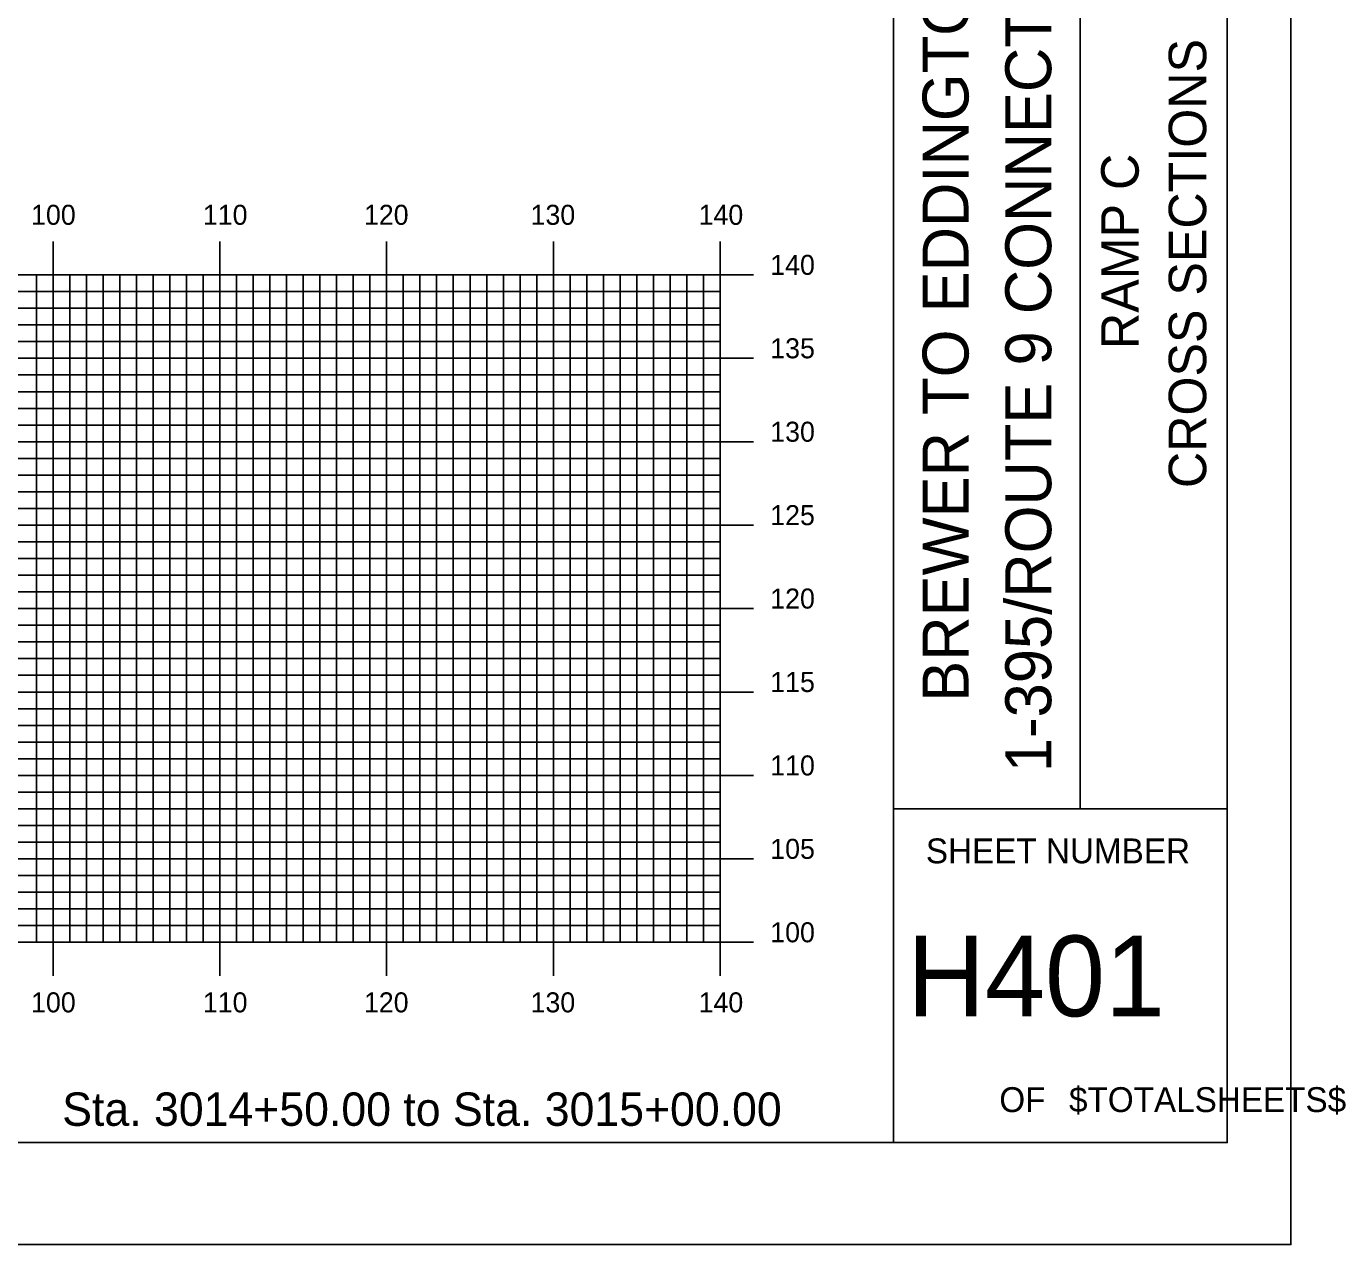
# Model space of a CAD drawing. Extents: x 1684799 to 1685142, y 461260 to 461480.
# Drawn here: x 1685063.1 to 1685142.2, y 461260 to 461333 of the extents above; entities that cross this region are included whole.
import ezdxf

# ---------------------------------------------------------------- set-up
doc = ezdxf.new("R2010")
doc.units = 0
for name, color, linetype in [('BORDER', 7, 'Continuous'), ('H_V ANNOTATION', 7, 'Continuous'), ('MAJOR', 7, 'Continuous'), ('MINOR', 7, 'Continuous'), ('PLOT BOUNDARY', 7, 'Continuous')]:
    doc.layers.add(name, color=color, linetype=linetype)

msp = doc.modelspace()

# ---------------------------------------------------------------- linework, layer by layer
at = {"layer": 'BORDER'}
for p, q in [((1685115.116, 461266.072), (1685115.116, 461476.072)), ((1685126.298, 461286.078), (1685126.298, 461356.078)), ((1685115.116, 461286.078), (1685135.116, 461286.078))]:
    msp.add_line(p, q, dxfattribs=at)
msp.add_lwpolyline([(1684815.116, 461266.072), (1685135.116, 461266.072), (1685135.116, 461476.072), (1684815.116, 461476.072)], close=True, dxfattribs=at)
at = {"layer": 'MAJOR'}
for p, q in [((1685064.716, 461320.076), (1685064.716, 461318.072)), ((1685074.716, 461320.076), (1685074.716, 461318.072)), ((1685084.716, 461320.076), (1685084.716, 461318.072)), ((1685094.716, 461320.076), (1685094.716, 461318.072)), ((1685104.716, 461320.076), (1685104.716, 461318.072)), ((1684824.716, 461318.072), (1685104.716, 461318.072)), ((1684824.716, 461318.072), (1685104.716, 461318.072)), ((1685064.716, 461278.072), (1685064.716, 461318.072)), ((1685074.716, 461278.072), (1685074.716, 461318.072)), ((1685084.716, 461278.072), (1685084.716, 461318.072)), ((1685094.716, 461278.072), (1685094.716, 461318.072)), ((1685106.72, 461318.072), (1685102.712, 461318.072)), ((1685104.716, 461278.072), (1685104.716, 461318.072)), ((1685104.716, 461278.072), (1685104.716, 461318.072)), ((1684824.716, 461313.072), (1685104.716, 461313.072)), ((1685106.72, 461313.072), (1685102.712, 461313.072)), ((1684824.716, 461308.072), (1685104.716, 461308.072)), ((1685106.72, 461308.072), (1685102.712, 461308.072)), ((1684824.716, 461303.072), (1685104.716, 461303.072)), ((1685106.72, 461303.072), (1685102.712, 461303.072)), ((1684824.716, 461298.072), (1685104.716, 461298.072)), ((1685106.72, 461298.072), (1685102.712, 461298.072)), ((1684824.716, 461293.072), (1685104.716, 461293.072)), ((1685106.72, 461293.072), (1685102.712, 461293.072)), ((1684824.716, 461288.072), (1685104.716, 461288.072)), ((1685106.72, 461288.072), (1685102.712, 461288.072)), ((1684824.716, 461283.072), (1685104.716, 461283.072)), ((1685106.72, 461283.072), (1685102.712, 461283.072)), ((1684824.716, 461278.072), (1685104.716, 461278.072)), ((1684824.716, 461278.072), (1685104.716, 461278.072)), ((1685064.716, 461276.068), (1685064.716, 461278.072)), ((1685074.716, 461276.068), (1685074.716, 461278.072)), ((1685084.716, 461276.068), (1685084.716, 461278.072)), ((1685094.716, 461276.068), (1685094.716, 461278.072)), ((1685106.72, 461278.072), (1685102.712, 461278.072)), ((1685104.716, 461276.068), (1685104.716, 461278.072))]:
    msp.add_line(p, q, dxfattribs=at)
at = {"layer": 'MINOR'}
for p, q in [((1685063.716, 461278.072), (1685063.716, 461318.072)), ((1685065.716, 461278.072), (1685065.716, 461318.072)), ((1685066.716, 461278.072), (1685066.716, 461318.072)), ((1685067.716, 461278.072), (1685067.716, 461318.072)), ((1685068.716, 461278.072), (1685068.716, 461318.072)), ((1685069.716, 461278.072), (1685069.716, 461318.072)), ((1685070.716, 461278.072), (1685070.716, 461318.072)), ((1685071.716, 461278.072), (1685071.716, 461318.072)), ((1685072.716, 461278.072), (1685072.716, 461318.072)), ((1685073.716, 461278.072), (1685073.716, 461318.072)), ((1685075.716, 461278.072), (1685075.716, 461318.072)), ((1685076.716, 461278.072), (1685076.716, 461318.072)), ((1685077.716, 461278.072), (1685077.716, 461318.072)), ((1685078.716, 461278.072), (1685078.716, 461318.072)), ((1685079.716, 461278.072), (1685079.716, 461318.072)), ((1685080.716, 461278.072), (1685080.716, 461318.072)), ((1685081.716, 461278.072), (1685081.716, 461318.072)), ((1685082.716, 461278.072), (1685082.716, 461318.072)), ((1685083.716, 461278.072), (1685083.716, 461318.072)), ((1685085.716, 461278.072), (1685085.716, 461318.072)), ((1685086.716, 461278.072), (1685086.716, 461318.072)), ((1685087.716, 461278.072), (1685087.716, 461318.072)), ((1685088.716, 461278.072), (1685088.716, 461318.072)), ((1685089.716, 461278.072), (1685089.716, 461318.072)), ((1685090.716, 461278.072), (1685090.716, 461318.072)), ((1685091.716, 461278.072), (1685091.716, 461318.072)), ((1685092.716, 461278.072), (1685092.716, 461318.072)), ((1685093.716, 461278.072), (1685093.716, 461318.072)), ((1685095.716, 461278.072), (1685095.716, 461318.072)), ((1685096.716, 461278.072), (1685096.716, 461318.072)), ((1685097.716, 461278.072), (1685097.716, 461318.072)), ((1685098.716, 461278.072), (1685098.716, 461318.072)), ((1685099.716, 461278.072), (1685099.716, 461318.072)), ((1685100.716, 461278.072), (1685100.716, 461318.072)), ((1685101.716, 461278.072), (1685101.716, 461318.072)), ((1685102.716, 461278.072), (1685102.716, 461318.072)), ((1685103.716, 461278.072), (1685103.716, 461318.072)), ((1684824.716, 461317.072), (1685104.716, 461317.072)), ((1685104.716, 461317.072), (1685102.712, 461317.072)), ((1684824.716, 461316.072), (1685104.716, 461316.072)), ((1685104.716, 461316.072), (1685102.712, 461316.072)), ((1684824.716, 461315.072), (1685104.716, 461315.072)), ((1685104.716, 461315.072), (1685102.712, 461315.072)), ((1684824.716, 461314.072), (1685104.716, 461314.072)), ((1685104.716, 461314.072), (1685102.712, 461314.072)), ((1684824.716, 461312.072), (1685104.716, 461312.072)), ((1685104.716, 461312.072), (1685102.712, 461312.072)), ((1684824.716, 461311.072), (1685104.716, 461311.072)), ((1685104.716, 461311.072), (1685102.712, 461311.072)), ((1684824.716, 461310.072), (1685104.716, 461310.072)), ((1685104.716, 461310.072), (1685102.712, 461310.072)), ((1684824.716, 461309.072), (1685104.716, 461309.072)), ((1685104.716, 461309.072), (1685102.712, 461309.072)), ((1684824.716, 461307.072), (1685104.716, 461307.072)), ((1685104.716, 461307.072), (1685102.712, 461307.072)), ((1684824.716, 461306.072), (1685104.716, 461306.072)), ((1685104.716, 461306.072), (1685102.712, 461306.072)), ((1684824.716, 461305.072), (1685104.716, 461305.072)), ((1685104.716, 461305.072), (1685102.712, 461305.072)), ((1684824.716, 461304.072), (1685104.716, 461304.072)), ((1685104.716, 461304.072), (1685102.712, 461304.072)), ((1684824.716, 461302.072), (1685104.716, 461302.072)), ((1685104.716, 461302.072), (1685102.712, 461302.072)), ((1684824.716, 461301.072), (1685104.716, 461301.072)), ((1685104.716, 461301.072), (1685102.712, 461301.072)), ((1684824.716, 461300.072), (1685104.716, 461300.072)), ((1685104.716, 461300.072), (1685102.712, 461300.072)), ((1684824.716, 461299.072), (1685104.716, 461299.072)), ((1685104.716, 461299.072), (1685102.712, 461299.072)), ((1684824.716, 461297.072), (1685104.716, 461297.072)), ((1685104.716, 461297.072), (1685102.712, 461297.072)), ((1684824.716, 461296.072), (1685104.716, 461296.072)), ((1685104.716, 461296.072), (1685102.712, 461296.072)), ((1684824.716, 461295.072), (1685104.716, 461295.072)), ((1685104.716, 461295.072), (1685102.712, 461295.072)), ((1684824.716, 461294.072), (1685104.716, 461294.072)), ((1685104.716, 461294.072), (1685102.712, 461294.072)), ((1684824.716, 461292.072), (1685104.716, 461292.072)), ((1685104.716, 461292.072), (1685102.712, 461292.072)), ((1684824.716, 461291.072), (1685104.716, 461291.072)), ((1685104.716, 461291.072), (1685102.712, 461291.072)), ((1684824.716, 461290.072), (1685104.716, 461290.072)), ((1685104.716, 461290.072), (1685102.712, 461290.072)), ((1684824.716, 461289.072), (1685104.716, 461289.072)), ((1685104.716, 461289.072), (1685102.712, 461289.072)), ((1684824.716, 461287.072), (1685104.716, 461287.072)), ((1685104.716, 461287.072), (1685102.712, 461287.072)), ((1684824.716, 461286.072), (1685104.716, 461286.072)), ((1685104.716, 461286.072), (1685102.712, 461286.072)), ((1684824.716, 461285.072), (1685104.716, 461285.072)), ((1685104.716, 461285.072), (1685102.712, 461285.072)), ((1684824.716, 461284.072), (1685104.716, 461284.072)), ((1685104.716, 461284.072), (1685102.712, 461284.072)), ((1684824.716, 461282.072), (1685104.716, 461282.072)), ((1685104.716, 461282.072), (1685102.712, 461282.072)), ((1684824.716, 461281.072), (1685104.716, 461281.072)), ((1685104.716, 461281.072), (1685102.712, 461281.072)), ((1684824.716, 461280.072), (1685104.716, 461280.072)), ((1685104.716, 461280.072), (1685102.712, 461280.072)), ((1684824.716, 461279.072), (1685104.716, 461279.072)), ((1685104.716, 461279.072), (1685102.712, 461279.072))]:
    msp.add_line(p, q, dxfattribs=at)
at = {"layer": 'PLOT BOUNDARY'}
msp.add_lwpolyline([(1684798.93, 461259.954), (1685138.93, 461259.954), (1685138.93, 461479.954), (1684798.93, 461479.954)], close=True, dxfattribs=at)

# ---------------------------------------------------------------- texts
at = {"layer": 'BORDER'}
for s, height, p in [('1-395/ROUTE 9 CONNECTOR', 2.75575, (1685124.565, 461288.272)), ('BREWER TO EDDINGTON', 2.75575, (1685119.605, 461292.481)), ('CROSS SECTIONS', 2.25, (1685133.857, 461305.294)), ('RAMP C', 2.25, (1685129.807, 461313.629))]:
    msp.add_text(s, height=height, rotation=90, dxfattribs=at).set_placement(p)
for s, height, p in [('SHEET NUMBER', 1.49054, (1685117.047, 461282.805)), ('H401', 4.8388, (1685115.918, 461273.637)), ('OF', 1.4905, (1685121.45, 461267.898)), ('$TOTALSHEETS$', 1.49054, (1685125.629, 461267.898))]:
    msp.add_text(s, height=height, dxfattribs=at).set_placement(p)
at = {"layer": 'H_V ANNOTATION'}
for s, height, p in [('100', 1.2, (1685063.4, 461321.072)), ('110', 1.2, (1685073.7, 461321.072)), ('120', 1.2, (1685083.357, 461321.072)), ('130', 1.2, (1685093.346, 461321.072)), ('140', 1.2, (1685103.421, 461321.072)), ('140', 1.2, (1685107.716, 461318.072)), ('135', 1.2, (1685107.716, 461313.072)), ('130', 1.2, (1685107.716, 461308.072)), ('125', 1.2, (1685107.716, 461303.072)), ('120', 1.2, (1685107.716, 461298.072)), ('115', 1.2, (1685107.716, 461293.072)), ('110', 1.2, (1685107.716, 461288.072)), ('105', 1.2, (1685107.716, 461283.072)), ('100', 1.2, (1685107.716, 461278.072)), ('100', 1.2, (1685063.4, 461273.872)), ('110', 1.2, (1685073.7, 461273.872)), ('120', 1.2, (1685083.357, 461273.872)), ('130', 1.2, (1685093.346, 461273.872)), ('140', 1.2, (1685103.421, 461273.872)), ('Sta. 3014+50.00 to Sta. 3015+00.00', 2.0004, (1685065.269, 461267.072))]:
    msp.add_text(s, height=height, dxfattribs=at).set_placement(p)

doc.saveas('drawing.dxf')
